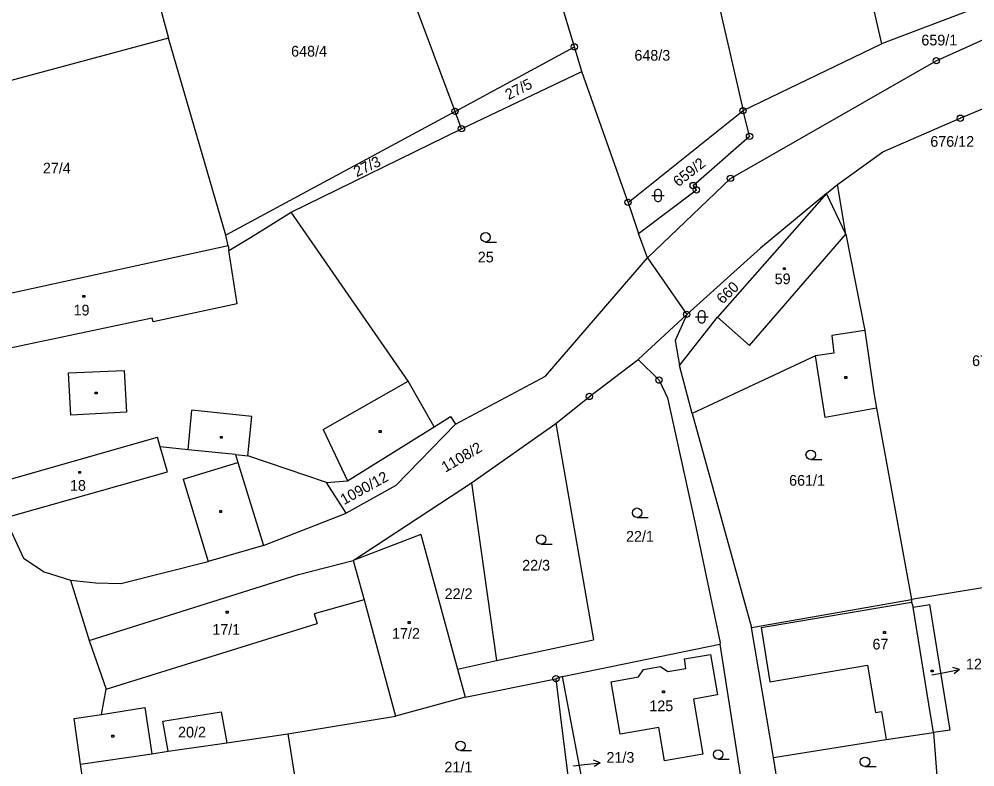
# Model space of a CAD drawing. Extents: x -794142 to -791199, y -1109267 to -1105626.
# Drawn here: x -793464.4 to -793312.7, y -1107676.8 to -1107558.1 of the extents above; entities that cross this region are included whole.
import ezdxf

# ---------------------------------------------------------------- set-up
doc = ezdxf.new("R2010")
doc.units = 0
for name, color, linetype in [('Komunikace', 7, 'Continuous'), ('Vrstva 1', 7, 'Continuous'), ('Vrstva 14', 7, 'Continuous'), ('Vrstva 15', 7, 'Continuous'), ('Vrstva 16', 7, 'Continuous'), ('Vrstva 2', 7, 'Continuous'), ('Vrstva 23', 7, 'Continuous'), ('Vrstva 25', 7, 'Continuous'), ('Vrstva 28', 7, 'Continuous')]:
    doc.layers.add(name, color=color, linetype=linetype)

msp = doc.modelspace()

# ---------------------------------------------------------------- linework, layer by layer
at = {"layer": 'Komunikace'}
for p, q in [((-793319.54, -1107662.23), (-793318.06, -1107661.93)), ((-793376.42, -1107676.66), (-793375.16, -1107676.51))]:
    msp.add_line(p, q, dxfattribs=at)
at = {"layer": 'Vrstva 1'}
for p, q in [((-793338.31, -1107515.86), (-793327.5, -1107562.01)), ((-793376.27, -1107562.47), (-793385.8, -1107530.91)), ((-793395.22, -1107572.72), (-793407.78, -1107539.04)), ((-793354.93, -1107548.78), (-793349.5, -1107572.6)), ((-793318.83, -1107564.67), (-793286.77, -1107550.24)), ((-793443.16, -1107552.13), (-793440.7, -1107561.08)), ((-793302.15, -1107552.37), (-793327.5, -1107562.01)), ((-793440.7, -1107561.08), (-793475.75, -1107570.55)), ((-793431.62, -1107592.4), (-793440.7, -1107561.08)), ((-793349.5, -1107572.6), (-793327.5, -1107562.01)), ((-793395.22, -1107572.72), (-793376.27, -1107562.47)), ((-793375.09, -1107566.4), (-793376.27, -1107562.47)), ((-793351.5, -1107583.36), (-793318.83, -1107564.67)), ((-793394.2, -1107575.47), (-793375.09, -1107566.4)), ((-793367.75, -1107587.18), (-793375.09, -1107566.4)), ((-793315.01, -1107573.81), (-793307.92, -1107570.8)), ((-793395.22, -1107572.72), (-793431.62, -1107592.4)), ((-793394.2, -1107575.47), (-793395.22, -1107572.72)), ((-793367.75, -1107587.18), (-793349.5, -1107572.6)), ((-793348.47, -1107576.68), (-793349.5, -1107572.6)), ((-793327.3, -1107579.16), (-793315.01, -1107573.81)), ((-793421.23, -1107588.72), (-793394.2, -1107575.47)), ((-793357.42, -1107584.5), (-793348.47, -1107576.68)), ((-793334.52, -1107584.36), (-793327.3, -1107579.16)), ((-793364.66, -1107595.96), (-793351.5, -1107583.36)), ((-793356.9, -1107585.19), (-793357.42, -1107584.5)), ((-793336.26, -1107585.74), (-793334.52, -1107584.36)), ((-793333.2, -1107592.21), (-793334.52, -1107584.36)), ((-793366.12, -1107592.11), (-793356.9, -1107585.19)), ((-793336.26, -1107585.74), (-793353.54, -1107605.43)), ((-793336.26, -1107585.74), (-793346.72, -1107594.44)), ((-793367.75, -1107587.18), (-793366.12, -1107592.11)), ((-793427.69, -1107592.74), (-793421.23, -1107588.72)), ((-793402.68, -1107615.57), (-793421.23, -1107588.72)), ((-793431.25, -1107594.06), (-793431.62, -1107592.4)), ((-793364.66, -1107595.96), (-793366.12, -1107592.11)), ((-793333.2, -1107592.21), (-793330.14, -1107607.51)), ((-793431.25, -1107594.06), (-793465.58, -1107601.57)), ((-793431.25, -1107594.06), (-793431.13, -1107594.81)), ((-793431.13, -1107594.81), (-793427.69, -1107592.74)), ((-793346.72, -1107594.44), (-793358.44, -1107604.97)), ((-793380.87, -1107614.8), (-793364.66, -1107595.96)), ((-793364.66, -1107595.96), (-793358.44, -1107604.97)), ((-793366.15, -1107612.13), (-793358.44, -1107604.97)), ((-793358.44, -1107604.97), (-793360.28, -1107609.12)), ((-793359.57, -1107613.06), (-793353.54, -1107605.43)), ((-793330.14, -1107607.51), (-793328.74, -1107617.43)), ((-793360.28, -1107609.12), (-793359.57, -1107613.06)), ((-793373.89, -1107618), (-793366.15, -1107612.13)), ((-793366.15, -1107612.13), (-793362.83, -1107615.4)), ((-793337.98, -1107611.52), (-793357.59, -1107620.72)), ((-793336.46, -1107621.35), (-793337.98, -1107611.52)), ((-793357.59, -1107620.72), (-793359.57, -1107613.06)), ((-793395.13, -1107622.4), (-793380.87, -1107614.8)), ((-793398.54, -1107622.84), (-793402.68, -1107615.57)), ((-793362.83, -1107615.4), (-793361.49, -1107618.22)), ((-793379.21, -1107622.3), (-793373.89, -1107618)), ((-793361.49, -1107618.22), (-793357.17, -1107637.95)), ((-793328.74, -1107617.43), (-793328.29, -1107619.87)), ((-793328.29, -1107619.87), (-793336.46, -1107621.35)), ((-793328.29, -1107619.87), (-793322.75, -1107650.23)), ((-793398.54, -1107622.84), (-793395.93, -1107621.2)), ((-793395.93, -1107621.2), (-793395.13, -1107622.4)), ((-793357.59, -1107620.72), (-793348.14, -1107654.68)), ((-793412.27, -1107631.4), (-793398.54, -1107622.84)), ((-793395.13, -1107622.4), (-793404.6, -1107632.13)), ((-793392.62, -1107631.74), (-793379.21, -1107622.3)), ((-793379.21, -1107622.3), (-793373.24, -1107656.63)), ((-793468.37, -1107631.84), (-793442.45, -1107624.47)), ((-793442.01, -1107626), (-793442.45, -1107624.47)), ((-793437.59, -1107626.45), (-793442.01, -1107626)), ((-793430.08, -1107627.22), (-793437.59, -1107626.45)), ((-793430.08, -1107627.22), (-793428.09, -1107627.44)), ((-793415.63, -1107631.66), (-793428.09, -1107627.44)), ((-793415.63, -1107631.66), (-793412.27, -1107631.4)), ((-793412.53, -1107636.55), (-793415.63, -1107631.66)), ((-793411.41, -1107644.03), (-793392.62, -1107631.74)), ((-793392.62, -1107631.74), (-793388.64, -1107659.95)), ((-793404.6, -1107632.13), (-793412.53, -1107636.55)), ((-793425.63, -1107641.64), (-793412.53, -1107636.55)), ((-793466.69, -1107637.27), (-793463.74, -1107643.66)), ((-793357.17, -1107637.95), (-793353.14, -1107657.14)), ((-793400.63, -1107639.94), (-793411.41, -1107644.03)), ((-793400.63, -1107639.94), (-793394.83, -1107661.3)), ((-793425.63, -1107641.64), (-793434.39, -1107644.22)), ((-793463.74, -1107643.66), (-793460.46, -1107645.87)), ((-793420.07, -1107646.27), (-793411.41, -1107644.03)), ((-793411.41, -1107644.03), (-793409.67, -1107650.31)), ((-793448.28, -1107647.71), (-793434.39, -1107644.22)), ((-793292.46, -1107645.29), (-793322.75, -1107650.23)), ((-793460.46, -1107645.87), (-793456.25, -1107647.17)), ((-793456.25, -1107647.17), (-793453.31, -1107656.74)), ((-793456.25, -1107647.17), (-793452.25, -1107647.6)), ((-793453.31, -1107656.74), (-793420.07, -1107646.27)), ((-793452.25, -1107647.6), (-793448.28, -1107647.71)), ((-793348.14, -1107654.68), (-793322.75, -1107650.23)), ((-793322.75, -1107650.23), (-793322.76, -1107650.66)), ((-793409.67, -1107650.31), (-793404.65, -1107668.79)), ((-793322.76, -1107650.66), (-793322.49, -1107651.47)), ((-793322.49, -1107651.47), (-793319.87, -1107651.05)), ((-793320, -1107666.84), (-793322.49, -1107651.47)), ((-793316.6, -1107671), (-793319.87, -1107651.05)), ((-793344.69, -1107675.35), (-793348.14, -1107654.68)), ((-793453.31, -1107656.74), (-793450.63, -1107664.5)), ((-793388.64, -1107659.95), (-793373.24, -1107656.63)), ((-793378.14, -1107662.48), (-793353.19, -1107657.31)), ((-793353.14, -1107657.14), (-793353.19, -1107657.31)), ((-793353.19, -1107657.31), (-793349.77, -1107679.43)), ((-793358.82, -1107659.69), (-793354.67, -1107658.97)), ((-793354.67, -1107658.97), (-793353.56, -1107665.36)), ((-793394.83, -1107661.3), (-793388.64, -1107659.95)), ((-793358.56, -1107661.19), (-793358.82, -1107659.69)), ((-793394.83, -1107661.3), (-793393.62, -1107665.74)), ((-793366.12, -1107662.53), (-793365.29, -1107661.35)), ((-793365.29, -1107661.35), (-793362.59, -1107660.87)), ((-793362.59, -1107660.87), (-793361.45, -1107661.69)), ((-793361.45, -1107661.69), (-793358.56, -1107661.19)), ((-793393.62, -1107665.74), (-793379.21, -1107662.83)), ((-793378.14, -1107662.48), (-793379.21, -1107662.83)), ((-793379.21, -1107662.83), (-793378.57, -1107668.07)), ((-793374.43, -1107682.16), (-793378.14, -1107662.48)), ((-793370.46, -1107663.3), (-793366.12, -1107662.53)), ((-793368.99, -1107671.63), (-793370.46, -1107663.3)), ((-793451.37, -1107668.51), (-793450.63, -1107664.5)), ((-793353.56, -1107665.36), (-793357.35, -1107666.05)), ((-793393.62, -1107665.74), (-793404.65, -1107668.79)), ((-793357.35, -1107666.05), (-793355.88, -1107674.78)), ((-793319.26, -1107671.37), (-793320, -1107666.84)), ((-793441.63, -1107669.56), (-793432.33, -1107668.09)), ((-793432.33, -1107668.09), (-793431.43, -1107672.98)), ((-793378.57, -1107668.07), (-793378.19, -1107671.12)), ((-793455.68, -1107669.13), (-793451.37, -1107668.51)), ((-793454.66, -1107676.39), (-793455.68, -1107669.13)), ((-793440.77, -1107674.35), (-793441.63, -1107669.56)), ((-793421.77, -1107671.56), (-793404.65, -1107668.79)), ((-793378.19, -1107671.12), (-793376.81, -1107682.29)), ((-793362.89, -1107670.58), (-793368.99, -1107671.63)), ((-793361.95, -1107675.84), (-793362.89, -1107670.58)), ((-793326.8, -1107672.5), (-793319.26, -1107671.37)), ((-793316.6, -1107671), (-793319.26, -1107671.37)), ((-793319.26, -1107671.37), (-793318.5, -1107681.47)), ((-793440.77, -1107674.35), (-793431.43, -1107672.98)), ((-793431.43, -1107672.98), (-793421.77, -1107671.56)), ((-793421.77, -1107671.56), (-793420.56, -1107679.22)), ((-793344.69, -1107675.35), (-793326.8, -1107672.5)), ((-793443.33, -1107674.73), (-793440.77, -1107674.35)), ((-793454.66, -1107676.39), (-793443.33, -1107674.73)), ((-793355.88, -1107674.78), (-793361.95, -1107675.84)), ((-793342.97, -1107685.65), (-793344.69, -1107675.35)), ((-793453.57, -1107684.14), (-793454.66, -1107676.39))]:
    msp.add_line(p, q, dxfattribs=at)
at = {"layer": 'Vrstva 16'}
for p, q in [((-793318.06, -1107661.93), (-793315.119, -1107661.337)), ((-793315.119, -1107661.337), (-793316.198, -1107661.045)), ((-793315.119, -1107661.337), (-793316, -1107662.025)), ((-793372.18, -1107676.158), (-793373.232, -1107675.779)), ((-793375.16, -1107676.51), (-793372.18, -1107676.158)), ((-793372.18, -1107676.158), (-793373.115, -1107676.772))]:
    msp.add_line(p, q, dxfattribs=at)
at = {"layer": 'Vrstva 2'}
for p, q in [((-793333.2, -1107592.21), (-793336.26, -1107585.74)), ((-793348.48, -1107609.89), (-793333.2, -1107592.21)), ((-793429.79, -1107603.3), (-793431.13, -1107594.81)), ((-793429.79, -1107603.3), (-793443.17, -1107606.17)), ((-793443.32, -1107605.55), (-793477.9, -1107612.84)), ((-793443.17, -1107606.17), (-793443.32, -1107605.55)), ((-793353.54, -1107605.43), (-793348.48, -1107609.89)), ((-793330.14, -1107607.51), (-793335.38, -1107608.32)), ((-793335.38, -1107608.32), (-793335.07, -1107611.12)), ((-793335.07, -1107611.12), (-793337.98, -1107611.52)), ((-793456.58, -1107614.27), (-793447.74, -1107613.9)), ((-793456.21, -1107620.96), (-793456.58, -1107614.27)), ((-793447.74, -1107613.9), (-793447.37, -1107620.49)), ((-793416.13, -1107623.22), (-793402.68, -1107615.57)), ((-793447.37, -1107620.49), (-793456.21, -1107620.96)), ((-793437.59, -1107626.45), (-793436.98, -1107620.19)), ((-793427.49, -1107621.17), (-793436.98, -1107620.19)), ((-793428.09, -1107627.44), (-793427.49, -1107621.17)), ((-793416.13, -1107623.22), (-793412.27, -1107631.4)), ((-793440.87, -1107629.99), (-793442.01, -1107626)), ((-793430.08, -1107627.22), (-793429.7, -1107628.46)), ((-793438.39, -1107631.14), (-793429.7, -1107628.46)), ((-793429.7, -1107628.46), (-793425.63, -1107641.64)), ((-793466.69, -1107637.27), (-793440.87, -1107629.99)), ((-793438.39, -1107631.14), (-793434.39, -1107644.22)), ((-793409.67, -1107650.31), (-793417.61, -1107652.53)), ((-793346.63, -1107654.68), (-793322.76, -1107650.66)), ((-793417.61, -1107652.53), (-793417.1, -1107654.05)), ((-793450.63, -1107664.5), (-793417.1, -1107654.05)), ((-793346.63, -1107654.68), (-793345.26, -1107663.31)), ((-793345.26, -1107663.31), (-793329.76, -1107660.67)), ((-793329.76, -1107660.67), (-793328.48, -1107668.17)), ((-793451.37, -1107668.51), (-793444.45, -1107667.38)), ((-793444.45, -1107667.38), (-793443.33, -1107674.73)), ((-793328.48, -1107668.17), (-793327.51, -1107668.02)), ((-793327.51, -1107668.02), (-793326.8, -1107672.5))]:
    msp.add_line(p, q, dxfattribs=at)
at = {"layer": 'Vrstva 23'}
for p, q in [((-793364, -1107586.08), (-793362, -1107586.08)), ((-793363.5, -1107585.48), (-793363.4, -1107585.28)), ((-793363.5, -1107586.68), (-793363.5, -1107585.48)), ((-793363.4, -1107585.28), (-793363.3, -1107585.18)), ((-793363.3, -1107585.18), (-793363.1, -1107585.08)), ((-793363.1, -1107585.08), (-793362.9, -1107585.08)), ((-793362.9, -1107585.08), (-793362.7, -1107585.18)), ((-793362.7, -1107585.18), (-793362.6, -1107585.28)), ((-793362.6, -1107585.28), (-793362.5, -1107585.48)), ((-793362.5, -1107585.48), (-793362.5, -1107586.68)), ((-793363.4, -1107586.88), (-793363.5, -1107586.68)), ((-793363.3, -1107586.98), (-793363.4, -1107586.88)), ((-793363.1, -1107587.08), (-793363.3, -1107586.98)), ((-793362.9, -1107587.08), (-793363.1, -1107587.08)), ((-793362.7, -1107586.98), (-793362.9, -1107587.08)), ((-793362.6, -1107586.88), (-793362.7, -1107586.98)), ((-793362.5, -1107586.68), (-793362.6, -1107586.88)), ((-793390.37, -1107593.47), (-793388.62, -1107593.47)), ((-793356.55, -1107604.76), (-793356.45, -1107604.56)), ((-793356.45, -1107604.56), (-793356.35, -1107604.46)), ((-793356.35, -1107604.46), (-793356.15, -1107604.36)), ((-793356.15, -1107604.36), (-793355.95, -1107604.36)), ((-793355.95, -1107604.36), (-793355.75, -1107604.46)), ((-793355.75, -1107604.46), (-793355.65, -1107604.56)), ((-793355.65, -1107604.56), (-793355.55, -1107604.76)), ((-793357.05, -1107605.36), (-793355.05, -1107605.36)), ((-793356.55, -1107605.96), (-793356.55, -1107604.76)), ((-793356.45, -1107606.16), (-793356.55, -1107605.96)), ((-793356.35, -1107606.26), (-793356.45, -1107606.16)), ((-793355.65, -1107606.16), (-793355.75, -1107606.26)), ((-793355.55, -1107605.96), (-793355.65, -1107606.16)), ((-793355.55, -1107604.76), (-793355.55, -1107605.96)), ((-793356.15, -1107606.36), (-793356.35, -1107606.26)), ((-793355.95, -1107606.36), (-793356.15, -1107606.36)), ((-793355.75, -1107606.26), (-793355.95, -1107606.36)), ((-793338.76, -1107628), (-793337.01, -1107628)), ((-793366.31, -1107637.21), (-793364.56, -1107637.21)), ((-793381.56, -1107641.45), (-793379.81, -1107641.45)), ((-793394.37, -1107674.22), (-793392.62, -1107674.22)), ((-793353.46, -1107675.6), (-793351.71, -1107675.6)), ((-793330.14, -1107676.77), (-793328.39, -1107676.77))]:
    msp.add_line(p, q, dxfattribs=at)
for centre in [(-793390.37, -1107592.72), (-793338.76, -1107627.25), (-793366.31, -1107636.46), (-793381.56, -1107640.7), (-793394.37, -1107673.47), (-793353.46, -1107674.85), (-793330.14, -1107676.02)]:
    msp.add_circle(centre, 0.75, dxfattribs=at)
at = {"layer": 'Vrstva 25'}
for p, q in [((-793343.09, -1107597.55), (-793342.79, -1107597.55)), ((-793343.09, -1107597.85), (-793343.09, -1107597.55)), ((-793342.79, -1107597.85), (-793343.09, -1107597.85)), ((-793342.79, -1107597.55), (-793342.79, -1107597.85)), ((-793454.3, -1107601.95), (-793454, -1107601.95)), ((-793454.3, -1107602.25), (-793454.3, -1107601.95)), ((-793454, -1107602.25), (-793454.3, -1107602.25)), ((-793454, -1107601.95), (-793454, -1107602.25)), ((-793333.34, -1107614.85), (-793333.04, -1107614.85)), ((-793333.34, -1107615.15), (-793333.34, -1107614.85)), ((-793333.04, -1107615.15), (-793333.34, -1107615.15)), ((-793333.04, -1107614.85), (-793333.04, -1107615.15)), ((-793452.33, -1107617.29), (-793452.03, -1107617.29)), ((-793452.33, -1107617.59), (-793452.33, -1107617.29)), ((-793452.03, -1107617.59), (-793452.33, -1107617.59)), ((-793452.03, -1107617.29), (-793452.03, -1107617.59)), ((-793432.48, -1107624.34), (-793432.18, -1107624.34)), ((-793432.48, -1107624.64), (-793432.48, -1107624.34)), ((-793432.18, -1107624.34), (-793432.18, -1107624.64)), ((-793407.27, -1107623.4), (-793406.97, -1107623.4)), ((-793407.27, -1107623.7), (-793407.27, -1107623.4)), ((-793406.97, -1107623.7), (-793407.27, -1107623.7)), ((-793406.97, -1107623.4), (-793406.97, -1107623.7)), ((-793432.18, -1107624.64), (-793432.48, -1107624.64)), ((-793454.96, -1107629.9), (-793454.66, -1107629.9)), ((-793454.96, -1107630.2), (-793454.96, -1107629.9)), ((-793454.66, -1107630.2), (-793454.96, -1107630.2)), ((-793454.66, -1107629.9), (-793454.66, -1107630.2)), ((-793432.57, -1107636.11), (-793432.27, -1107636.11)), ((-793432.57, -1107636.41), (-793432.57, -1107636.11)), ((-793432.27, -1107636.41), (-793432.57, -1107636.41)), ((-793432.27, -1107636.11), (-793432.27, -1107636.41)), ((-793431.53, -1107652.1), (-793431.23, -1107652.1)), ((-793431.53, -1107652.4), (-793431.53, -1107652.1)), ((-793431.23, -1107652.4), (-793431.53, -1107652.4)), ((-793431.23, -1107652.1), (-793431.23, -1107652.4)), ((-793402.65, -1107653.73), (-793402.35, -1107653.73)), ((-793402.65, -1107654.03), (-793402.65, -1107653.73)), ((-793402.35, -1107654.03), (-793402.65, -1107654.03)), ((-793402.35, -1107653.73), (-793402.35, -1107654.03)), ((-793327.18, -1107655.35), (-793326.88, -1107655.35)), ((-793327.18, -1107655.65), (-793327.18, -1107655.35)), ((-793326.88, -1107655.65), (-793327.18, -1107655.65)), ((-793326.88, -1107655.35), (-793326.88, -1107655.65)), ((-793319.64, -1107661.45), (-793319.34, -1107661.45)), ((-793319.64, -1107661.75), (-793319.64, -1107661.45)), ((-793319.34, -1107661.75), (-793319.64, -1107661.75)), ((-793319.34, -1107661.45), (-793319.34, -1107661.75)), ((-793362.28, -1107664.77), (-793361.98, -1107664.77)), ((-793362.28, -1107665.07), (-793362.28, -1107664.77)), ((-793361.98, -1107665.07), (-793362.28, -1107665.07)), ((-793361.98, -1107664.77), (-793361.98, -1107665.07)), ((-793449.68, -1107671.81), (-793449.38, -1107671.81)), ((-793449.68, -1107672.11), (-793449.68, -1107671.81)), ((-793449.38, -1107672.11), (-793449.68, -1107672.11)), ((-793449.38, -1107671.81), (-793449.38, -1107672.11))]:
    msp.add_line(p, q, dxfattribs=at)
at = {"layer": 'Vrstva 28'}
for centre, radius in [((-793376.27, -1107562.47), 0.5), ((-793376.27, -1107562.47), 0.01), ((-793318.83, -1107564.67), 0.5), ((-793318.83, -1107564.67), 0.01), ((-793395.22, -1107572.72), 0.5), ((-793395.22, -1107572.72), 0.01), ((-793349.5, -1107572.6), 0.5), ((-793349.5, -1107572.6), 0.01), ((-793315.01, -1107573.81), 0.5), ((-793315.01, -1107573.81), 0.01), ((-793394.2, -1107575.47), 0.5), ((-793394.2, -1107575.47), 0.01), ((-793348.47, -1107576.68), 0.5), ((-793348.47, -1107576.68), 0.01), ((-793351.5, -1107583.36), 0.5), ((-793351.5, -1107583.36), 0.01), ((-793357.42, -1107584.5), 0.5), ((-793357.42, -1107584.5), 0.01), ((-793356.9, -1107585.19), 0.5), ((-793356.9, -1107585.19), 0.01), ((-793367.75, -1107587.18), 0.5), ((-793367.75, -1107587.18), 0.01), ((-793358.44, -1107604.97), 0.5), ((-793358.44, -1107604.97), 0.01), ((-793362.83, -1107615.4), 0.5), ((-793362.83, -1107615.4), 0.01), ((-793373.89, -1107618), 0.5), ((-793373.89, -1107618), 0.01), ((-793379.21, -1107662.83), 0.5), ((-793379.21, -1107662.83), 0.01)]:
    msp.add_circle(centre, radius, dxfattribs=at)

# ---------------------------------------------------------------- texts
at = {"layer": 'Vrstva 14'}
for s, height, p in [('659/1', 1.7, (-793321.19, -1107562.25)), ('648/4', 1.7, (-793421.241, -1107564.02)), ('648/3', 1.7, (-793366.746, -1107564.67)), ('27/4', 1.7, (-793460.652, -1107582.58)), ('25', 1.7, (-793391.61, -1107596.71)), ('676/1', 1.7, (-793313.14, -1107613.17)), ('661/1', 1.7, (-793342.186, -1107632.17)), ('22/1', 1.7, (-793368.073, -1107641.06)), ('22/3', 1.7, (-793384.56, -1107645.65)), ('22/2', 1.7, (-793396.869, -1107650.18)), ('20/2', 1.7, (-793439.189, -1107672.15)), ('21/1', 1.7, (-793396.906, -1107677.71)), ('21/3', 0.1, (-793376.567, -1107676.66))]:
    msp.add_text(s, height=height, dxfattribs=at).set_placement(p)
for s, rotation, p in [('27/5', 27.12132, (-793386.724, -1107570.947)), ('27/3', 25.54677, (-793410.834, -1107583.181)), ('659/2', 38.33334, (-793359.766, -1107584.797)), ('660', 43.74558, (-793352.748, -1107603.429)), ('1108/2', 30.33072, (-793396.752, -1107630.111)), ('1090/12', 28.96137, (-793412.83, -1107635.256))]:
    msp.add_text(s, height=1.7, rotation=rotation, dxfattribs=at).set_placement(p)
at = {"layer": 'Vrstva 15'}
for s, height, p in [('59', 1.7, (-793344.483, -1107600.17)), ('19', 1.7, (-793455.78, -1107605.13)), ('18', 1.7, (-793456.35, -1107632.98)), ('17/1', 1.7, (-793433.753, -1107655.85)), ('17/2', 1.7, (-793405.22, -1107656.48)), ('67', 1.7, (-793328.953, -1107658.18)), ('122', 0.1, (-793319.654, -1107662.23)), ('125', 1.7, (-793364.376, -1107667.98))]:
    msp.add_text(s, height=height, dxfattribs=at).set_placement(p)
at = {"layer": 'Vrstva 16'}
for s, p in [('676/12', (-793319.77, -1107578.35)), ('122', (-793314.12, -1107661.34)), ('21/3', (-793371.18, -1107676.16))]:
    msp.add_text(s, height=1.7, dxfattribs=at).set_placement(p)

doc.saveas('drawing.dxf')
